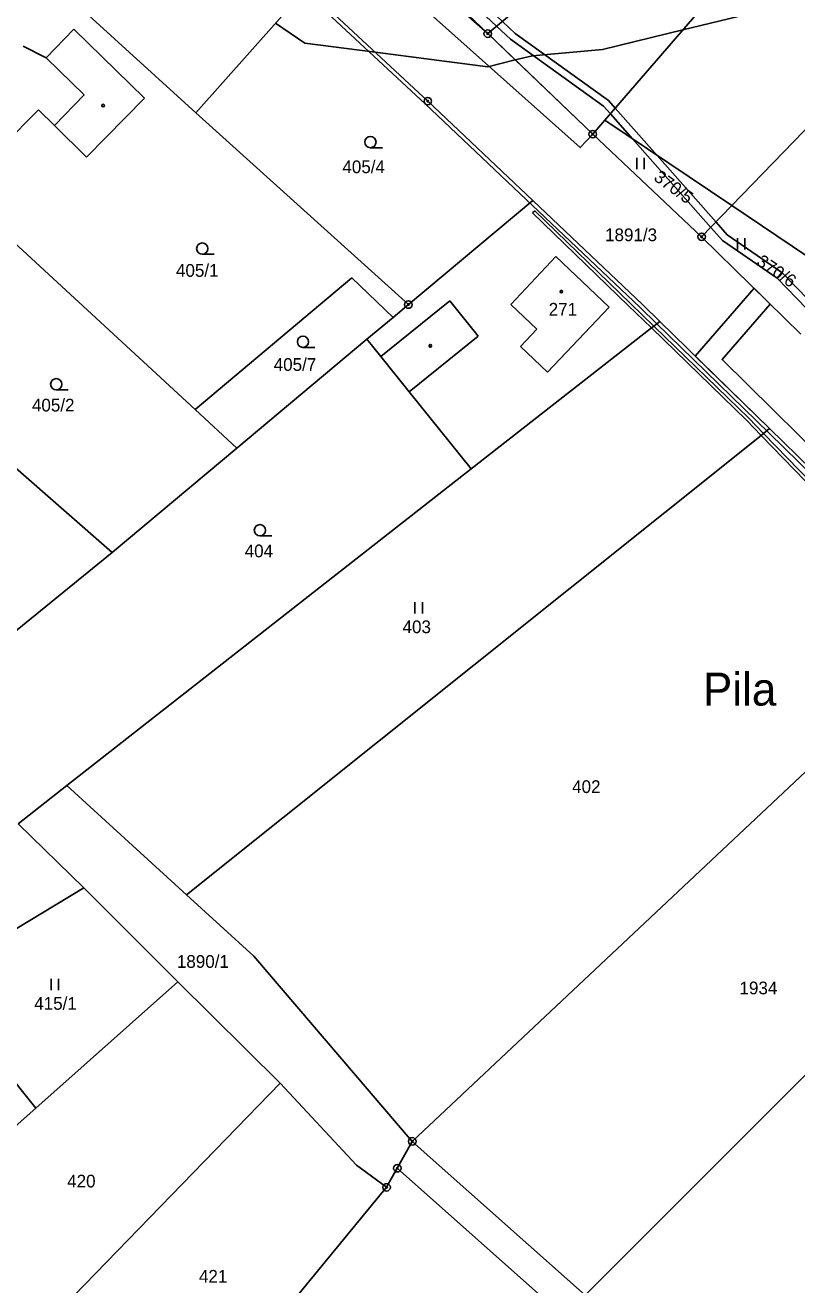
# Model space of a CAD drawing. Extents: x -445050 to -440454, y -1134563 to -1129741.
# Drawn here: x -442688.8 to -442585.7, y -1131200.4 to -1131032.1 of the extents above; entities that cross this region are included whole.
import ezdxf

# ---------------------------------------------------------------- set-up
doc = ezdxf.new("R2010")
doc.units = 0
for name, color, linetype in [('Vrstva 1', 7, 'Continuous'), ('Vrstva 15', 7, 'Continuous'), ('Vrstva 18', 7, 'Continuous'), ('Vrstva 19', 7, 'Continuous'), ('Vrstva 24', 7, 'Continuous'), ('Vrstva 25', 7, 'Continuous'), ('Vrstva 3', 7, 'Continuous'), ('Vrstva 30', 7, 'Continuous'), ('Vrstva 37', 7, 'Continuous'), ('Vrstva 4', 7, 'Continuous'), ('Vrstva 5', 7, 'Continuous'), ('Vrstva 52', 7, 'Continuous')]:
    doc.layers.add(name, color=color, linetype=linetype)

msp = doc.modelspace()

# ---------------------------------------------------------------- linework, layer by layer
at = {"layer": 'Vrstva 1'}
for points in [[(-442594.39, -1131056.19), (-442530.97, -1130990.64)], [(-442666.03, -1131043.8), (-442698.69, -1131014.07)], [(-442611.36, -1131044.77), (-442588.5, -1131018.32)], [(-442613.94, -1131022.3), (-442627.01, -1131033.21)], [(-442651.24, -1131027.12), (-442666.03, -1131043.8)], [(-442651.24, -1131027.12), (-442635.02, -1131042.23)], [(-442634.02, -1131026.47), (-442627.01, -1131033.21)], [(-442682.32, -1131032.62), (-442686.03, -1131036.43)], [(-442672.88, -1131041.85), (-442682.32, -1131032.62)], [(-442666.11, -1131083.42), (-442719.68, -1131034.05)], [(-442627.01, -1131033.21), (-442612.98, -1131046.64)], [(-442689.1, -1131034.89), (-442686.03, -1131036.43)], [(-442672.88, -1131041.85), (-442680.62, -1131049.7)], [(-442621, -1131055.51), (-442635.02, -1131042.23)], [(-442687.05, -1131043.38), (-442691.7, -1131048.11)], [(-442684.9, -1131045.48), (-442687.05, -1131043.38)], [(-442637.61, -1131069.41), (-442666.03, -1131043.8)], [(-442612.98, -1131046.64), (-442611.36, -1131044.77)], [(-442611.36, -1131044.77), (-442594.39, -1131056.19)], [(-442680.62, -1131049.7), (-442684.9, -1131045.48)], [(-442612.98, -1131046.64), (-442598.42, -1131060.36)], [(-442621, -1131055.51), (-442637.61, -1131069.41)], [(-442606.34, -1131069.4), (-442621, -1131055.51)], [(-442598.42, -1131060.36), (-442594.39, -1131056.19)], [(-442594.39, -1131056.19), (-442578.28, -1131067.04)], [(-442598.42, -1131060.36), (-442585.16, -1131073.36)], [(-442645.19, -1131065.84), (-442666.11, -1131083.42)], [(-442639.66, -1131071.13), (-442645.19, -1131065.84)], [(-442637.61, -1131069.41), (-442639.66, -1131071.13)], [(-442606.34, -1131069.4), (-442604.01, -1131071.66)], [(-442639.66, -1131071.13), (-442643.16, -1131074.05)], [(-442604.83, -1131072.3), (-442604.01, -1131071.66)], [(-442604.01, -1131071.66), (-442589.34, -1131085.99)], [(-442605.13, -1131072.54), (-442629.22, -1131091.38)], [(-442604.83, -1131072.3), (-442605.13, -1131072.54)], [(-442709.52, -1131074.26), (-442677.19, -1131102.53)], [(-442643.16, -1131074.05), (-442660.52, -1131088.58)], [(-442643.16, -1131074.05), (-442641.31, -1131076.35)], [(-442637.52, -1131081.07), (-442641.31, -1131076.35)], [(-442637.52, -1131081.07), (-442629.22, -1131091.38)], [(-442660.52, -1131088.58), (-442666.11, -1131083.42)], [(-442667.28, -1131148.27), (-442590.47, -1131086.89)], [(-442590.47, -1131086.89), (-442590.15, -1131086.64)], [(-442590.15, -1131086.64), (-442589.34, -1131085.99)], [(-442589.34, -1131085.99), (-442563.05, -1131111.66)], [(-442660.52, -1131088.58), (-442677.19, -1131102.53)], [(-442629.22, -1131091.38), (-442683.27, -1131133.69)], [(-442704.55, -1131124.76), (-442677.19, -1131102.53)], [(-442564.54, -1131113.06), (-442637.09, -1131181.23)], [(-442543.72, -1131131.48), (-442614.01, -1131201.79)], [(-442683.27, -1131133.69), (-442689.77, -1131138.78)], [(-442683.27, -1131133.69), (-442667.28, -1131148.27)], [(-442681, -1131147.35), (-442689.77, -1131138.78)], [(-442701.19, -1131159.55), (-442681, -1131147.35)], [(-442668.44, -1131159.93), (-442681, -1131147.35)], [(-442667.28, -1131148.27), (-442658.28, -1131156.47)], [(-442658.28, -1131156.47), (-442637.09, -1131181.23)], [(-442701.19, -1131159.55), (-442687.41, -1131176.77)], [(-442668.44, -1131159.93), (-442687.41, -1131176.77)], [(-442654.76, -1131173.47), (-442668.44, -1131159.93)], [(-442654.76, -1131173.47), (-442691.03, -1131210.88)], [(-442644.54, -1131184.4), (-442654.76, -1131173.47)], [(-442687.41, -1131176.77), (-442708.81, -1131195.76)], [(-442637.09, -1131181.23), (-442639.09, -1131184.82)], [(-442614.01, -1131201.79), (-442637.09, -1131181.23)], [(-442640.52, -1131187.37), (-442644.54, -1131184.4)], [(-442640.52, -1131187.37), (-442639.09, -1131184.82)], [(-442616.23, -1131205.18), (-442639.09, -1131184.82)], [(-442640.52, -1131187.37), (-442672.68, -1131226.49)]]:
    msp.add_lwpolyline(points, dxfattribs=at)
at = {"layer": 'Vrstva 24'}
for centre, radius in [((-442627.01, -1131033.21), 0.5), ((-442627.01, -1131033.21), 0.1), ((-442635.02, -1131042.23), 0.5), ((-442635.02, -1131042.23), 0.1), ((-442612.98, -1131046.64), 0.5), ((-442612.98, -1131046.64), 0.1), ((-442598.42, -1131060.36), 0.5), ((-442598.42, -1131060.36), 0.1), ((-442637.61, -1131069.41), 0.5), ((-442637.61, -1131069.41), 0.1), ((-442637.09, -1131181.23), 0.5), ((-442637.09, -1131181.23), 0.1), ((-442639.09, -1131184.82), 0.5), ((-442639.09, -1131184.82), 0.1), ((-442640.52, -1131187.37), 0.5), ((-442640.52, -1131187.37), 0.1)]:
    msp.add_circle(centre, radius, dxfattribs=at)
at = {"layer": 'Vrstva 25'}
for p, q in [((-442642.68, -1131048.45), (-442641.08, -1131048.45)), ((-442607.09, -1131051.31), (-442607.09, -1131049.81)), ((-442606.09, -1131051.31), (-442606.09, -1131049.81)), ((-442593.65, -1131062.06), (-442593.65, -1131060.56)), ((-442592.65, -1131062.06), (-442592.65, -1131060.56)), ((-442665.16, -1131062.68), (-442663.56, -1131062.68)), ((-442651.7, -1131075.13), (-442650.1, -1131075.13)), ((-442684.67, -1131080.81), (-442683.07, -1131080.81)), ((-442657.46, -1131100.32), (-442655.86, -1131100.32)), ((-442636.73, -1131110.68), (-442636.73, -1131109.18)), ((-442635.73, -1131110.68), (-442635.73, -1131109.18)), ((-442685.36, -1131161.01), (-442685.36, -1131159.51)), ((-442684.36, -1131161.01), (-442684.36, -1131159.51))]:
    msp.add_line(p, q, dxfattribs=at)
for centre, radius in [((-442678.4, -1131042.83), 0.175), ((-442642.68, -1131047.7), 0.75), ((-442665.16, -1131061.93), 0.75), ((-442617.17, -1131067.68), 0.175), ((-442651.7, -1131074.38), 0.75), ((-442634.68, -1131074.92), 0.175), ((-442684.67, -1131080.06), 0.75), ((-442657.46, -1131099.57), 0.75)]:
    msp.add_circle(centre, radius, dxfattribs=at)
at = {"layer": 'Vrstva 3'}
for points in [[(-442617.89, -1131063.01), (-442623.94, -1131069.4)], [(-442610.77, -1131069.74), (-442617.89, -1131063.01)], [(-442623.94, -1131069.4), (-442620.45, -1131072.7)], [(-442619.01, -1131078.46), (-442610.77, -1131069.74)], [(-442620.45, -1131072.7), (-442622.65, -1131075.03)], [(-442622.65, -1131075.03), (-442619.01, -1131078.46)]]:
    msp.add_lwpolyline(points, dxfattribs=at)
at = {"layer": 'Vrstva 30'}
for points in [[(-442595.65, -1131060.85), (-442597.2, -1131059.1), (-442607.66, -1131047.26), (-442610.62, -1131043.91), (-442611.53, -1131042.88), (-442623.98, -1131033.96), (-442625.83, -1131032.22), (-442639.58, -1131019.27), (-442646.22, -1131011.81), (-442653.27, -1131003.91), (-442652.53, -1131003.25), (-442645.59, -1131011.03), (-442638.86, -1131018.57), (-442625.05, -1131031.57), (-442623.34, -1131033.18), (-442610.85, -1131042.14), (-442609.96, -1131043.15), (-442604.37, -1131049.47), (-442596.5, -1131058.38), (-442594.99, -1131060.09)], [(-442646.11, -1131020.38), (-442652.31, -1131026.12), (-442654.51, -1131024.07), (-442646.15, -1131016.32), (-442627.01, -1131033.21), (-442624.35, -1131035.75), (-442612.98, -1131046.64), (-442614.64, -1131048.43), (-442646.11, -1131020.38)], [(-442620.73, -1131056.87), (-442607.95, -1131069.27), (-442604.83, -1131072.3), (-442605.13, -1131072.54), (-442608.21, -1131069.56), (-442621.01, -1131057.16)], [(-442621.01, -1131057.16), (-442620.73, -1131056.87)], [(-442594.99, -1131060.09), (-442587.69, -1131065.14), (-442588.33, -1131065.9), (-442595.65, -1131060.85)], [(-442551, -1131084.13), (-442551.77, -1131084.91), (-442558.06, -1131082.64), (-442568.66, -1131078.8), (-442579.61, -1131073.58), (-442581.95, -1131072.47), (-442583.01, -1131071.38), (-442588.33, -1131065.9), (-442587.69, -1131065.14), (-442582.27, -1131070.71), (-442581.35, -1131071.65), (-442578.89, -1131072.82), (-442568.28, -1131077.88), (-442557.19, -1131081.89), (-442551, -1131084.13)], [(-442599.27, -1131076.29), (-442591.41, -1131067.23), (-442589.26, -1131069.34), (-442595.69, -1131076.75), (-442527.43, -1131144.09), (-442520.74, -1131136.48), (-442518.48, -1131138.46), (-442525.29, -1131146.2), (-442461.79, -1131209.24), (-442462.86, -1131210.31), (-442464.63, -1131208.55), (-442487.64, -1131185.63), (-442493.86, -1131179.32), (-442520.52, -1131152.26), (-442522.17, -1131150.69), (-442543.02, -1131130.78), (-442563.05, -1131111.66), (-442589.34, -1131085.99), (-442599.27, -1131076.29)], [(-442592.44, -1131084.86), (-442605.13, -1131072.54), (-442604.83, -1131072.3), (-442592.13, -1131084.6), (-442590.15, -1131086.64), (-442567.86, -1131109.6), (-442564.25, -1131112.78), (-442564.54, -1131113.06), (-442568.34, -1131109.71), (-442590.47, -1131086.89), (-442592.44, -1131084.86)]]:
    msp.add_lwpolyline(points, dxfattribs=at)
at = {"layer": 'Vrstva 37'}
msp.add_circle((-442617.17, -1131067.68), 0.175, dxfattribs=at)
at = {"layer": 'Vrstva 4'}
for points in [[(-442686.03, -1131036.43), (-442680.95, -1131041.38)], [(-442680.95, -1131041.38), (-442684.9, -1131045.48)], [(-442617.89, -1131063.01), (-442623.94, -1131069.4)], [(-442610.77, -1131069.74), (-442617.89, -1131063.01)], [(-442632.08, -1131068.93), (-442641.31, -1131076.35)], [(-442628.29, -1131073.64), (-442632.08, -1131068.93)], [(-442623.94, -1131069.4), (-442620.45, -1131072.7)], [(-442619.01, -1131078.46), (-442610.77, -1131069.74)], [(-442620.45, -1131072.7), (-442622.65, -1131075.03)], [(-442637.52, -1131081.07), (-442628.29, -1131073.64)], [(-442622.65, -1131075.03), (-442619.01, -1131078.46)]]:
    msp.add_lwpolyline(points, dxfattribs=at)
at = {"layer": 'Vrstva 5'}
for points in [[(-442651.57, -1131027.49), (-442635.36, -1131042.6)], [(-442635.36, -1131042.6), (-442606.69, -1131069.76)], [(-442606.69, -1131069.76), (-442604.41, -1131071.97)], [(-442604.54, -1131071.85), (-442589.42, -1131086.61)], [(-442589.42, -1131086.61), (-442563.42, -1131112)]]:
    msp.add_lwpolyline(points, dxfattribs=at)
at = {"layer": 'Vrstva 52'}
msp.add_lwpolyline([(-442588.73, -1131029.78), (-442600.95, -1131032.72), (-442611.69, -1131035.31), (-442621.04, -1131036.16), (-442623.33, -1131036.73), (-442627, -1131037.65), (-442642.05, -1131035.68), (-442651.44, -1131034.46), (-442655.39, -1131031.8)], dxfattribs=at)

# ---------------------------------------------------------------- texts
at = {"layer": 'Vrstva 15'}
msp.add_text('Pila', height=4.4, dxfattribs=at).set_placement((-442598.25, -1131123))
at = {"layer": 'Vrstva 18'}
for s, p in [('405/4', (-442646.43, -1131051.85)), ('1891/3', (-442611.33, -1131060.94)), ('405/1', (-442668.67, -1131065.7)), ('405/7', (-442655.61, -1131078.27)), ('405/2', (-442687.92, -1131083.7)), ('404', (-442659.49, -1131103.18)), ('403', (-442638.39, -1131113.32)), ('402', (-442615.73, -1131134.68)), ('1890/1', (-442668.55, -1131158.04)), ('1934', (-442593.36, -1131161.58)), ('415/1', (-442687.61, -1131163.64)), ('420', (-442683.21, -1131187.39)), ('421', (-442665.6, -1131200.11))]:
    msp.add_text(s, height=1.7, dxfattribs=at).set_placement(p)
for s, rotation, p in [('370/5', 323.9937, (-442604.95, -1131052.7)), ('370/6', 325.7964, (-442591.23, -1131064.02))]:
    msp.add_text(s, height=1.7, rotation=rotation, dxfattribs=at).set_placement(p)
at = {"layer": 'Vrstva 19'}
msp.add_text('271', height=1.7, dxfattribs=at).set_placement((-442618.86, -1131070.89))

doc.saveas('drawing.dxf')
